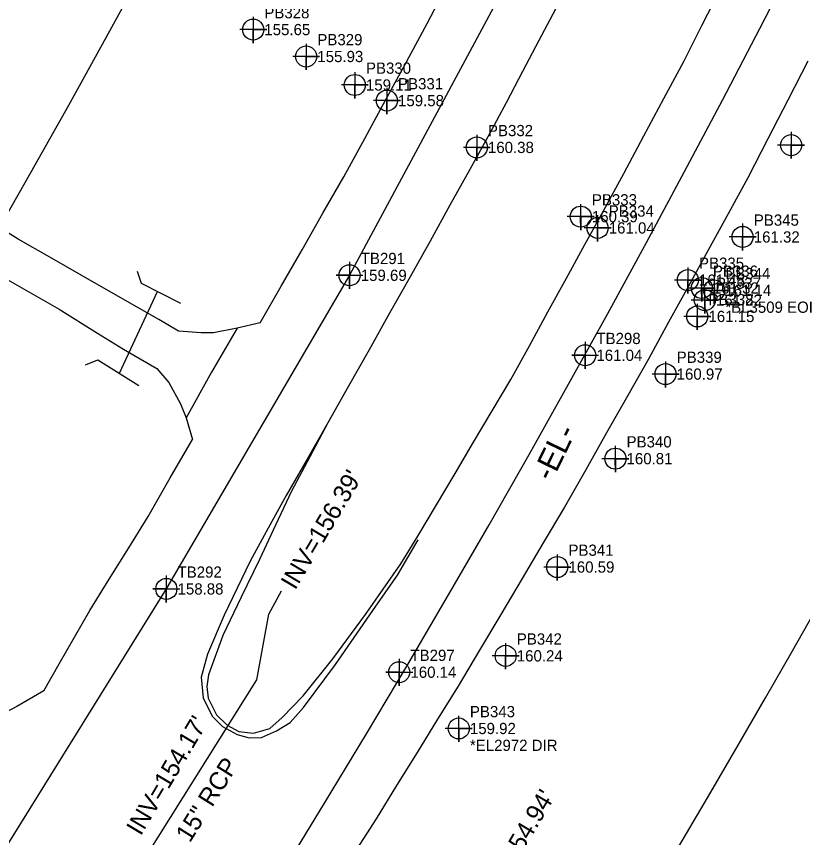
# Model space of a CAD drawing. Extents: x 2262665 to 2270527, y 505476 to 514960.
# Drawn here: x 2265830 to 2266005, y 508854 to 509036.7 of the extents above; entities that cross this region are included whole.
import ezdxf

# ---------------------------------------------------------------- set-up
doc = ezdxf.new("R2010")
doc.units = 0
for name, color, linetype in [('Exist Horizontal Alignment', 7, 'Continuous'), ('Exist Horizontal Alignment Direction Label', 7, 'Continuous'), ('Exist Right of Way Control of Access Line', 7, 'Continuous'), ('Exist Roads Change in Surface', 7, 'Continuous'), ('Exist Roads EOP', 7, 'Continuous'), ('Exist Roads EOP Other', 7, 'Continuous'), ('Exist Roads EOT', 7, 'Continuous'), ('Exist Roads EOT Cogo Elevation', 7, 'Continuous'), ('Exist Roads EOT Cogo Number', 7, 'Continuous'), ('Exist Roads EOT Cogo Point CELL', 7, 'Continuous'), ('Exist Structure Minor Culvert Topo', 7, 'Continuous'), ('Exist Structure Minor Head and End Wall', 7, 'Continuous'), ('Exist Structure Minor Pipes RCP 15 Inch', 7, 'Continuous'), ('Exist Structure Minor Pipes RCP 15 Inch Invert', 7, 'Continuous'), ('Exist Structure Minor Pipes RCP 15 Inch Leader', 7, 'Continuous'), ('Exist Structure Minor Pipes RCP 15 Inch Text', 7, 'Continuous'), ('Exist Utilities Telephone UG Cable SUE LOS C Cogo Comment', 7, 'Continuous'), ('Exist Utilities Telephone UG Cable SUE LOS C Cogo Elevation', 7, 'Continuous'), ('Exist Utilities Telephone UG Cable SUE LOS C Cogo Number', 7, 'Continuous'), ('Exist Utilities Telephone UG Cable SUE LOS C Cogo Point CELL', 7, 'Continuous'), ('Exist Utilities Telephone UG Conduit SUE LOS B Cogo Comment', 7, 'Continuous'), ('Exist Utilities Telephone UG Conduit SUE LOS B Cogo Elevation', 7, 'Continuous'), ('Exist Utilities Telephone UG Conduit SUE LOS B Cogo Number', 7, 'Continuous'), ('Exist Utilities Telephone UG Conduit SUE LOS B Cogo Point CELL', 7, 'Continuous')]:
    doc.layers.add(name, color=color, linetype=linetype)

msp = doc.modelspace()

# ---------------------------------------------------------------- linework, layer by layer
at = {"layer": 'Exist Horizontal Alignment'}
msp.add_arc((2263436.25, 510359.19), 2882, 309.60499, 355.6461, dxfattribs=at)
at = {"layer": 'Exist Right of Way Control of Access Line'}
for radius, end in [(2754.56, 355.6461), (2954.56, 339.73535)]:
    msp.add_arc((2263436.25, 510359.19), radius, 309.60499, end, dxfattribs=at)
at = {"layer": 'Exist Roads Change in Surface'}
msp.add_lwpolyline([(2265879.17, 508967.38), (2265873.46, 508957.58), (2265867.86, 508947.39)], dxfattribs=at)
at = {"layer": 'Exist Roads EOP'}
for points in [[(2265884.33, 508968.55), (2265888.98, 508976.67), (2265893.63, 508984.79), (2265898.28, 508992.91), (2265902.94, 509001.03), (2265907.58, 509009.55), (2265912.22, 509018.06), (2265916.86, 509026.58), (2265921.5, 509035.1), (2265927.16, 509046.11)], [(2265950.02, 509038.32), (2265946.36, 509031.38), (2265942.69, 509024.44), (2265939.03, 509017.5), (2265935.36, 509010.56), (2265930.94, 509002.62), (2265926.53, 508994.68), (2265922.11, 508986.74), (2265917.7, 508978.8), (2265913.12, 508970.67), (2265908.54, 508962.54), (2265903.96, 508954.41), (2265899.38, 508946.28), (2265895.32, 508938.69), (2265891.27, 508931.1), (2265887.72, 508923.5), (2265884.17, 508915.91), (2265880.07, 508907.46), (2265875.97, 508899), (2265872.78, 508890.2), (2265872.39, 508887.64), (2265872.74, 508885.01), (2265874.55, 508881.34), (2265876.97, 508879), (2265879.53, 508877.63), (2265882.84, 508877.23), (2265886.46, 508878.3), (2265889.21, 508880.7), (2265893.89, 508885.57), (2265900.48, 508893.74), (2265907.78, 508903.63), (2265911.68, 508909.28), (2265915.58, 508914.93), (2265919.39, 508921.1), (2265923.53, 508928.07), (2265927.68, 508935.04), (2265931.82, 508942.01), (2265935.96, 508948.98), (2265940.11, 508955.95), (2265944.23, 508963.45), (2265948.36, 508970.95), (2265952.49, 508978.45), (2265956.61, 508985.95), (2265960.74, 508993.45), (2265965.22, 509001.78), (2265969.7, 509010.12), (2265974.18, 509018.46), (2265978.66, 509026.8), (2265982.63, 509034.67), (2265986.61, 509042.54)], [(2266006.21, 509026.75), (2266001.77, 509018.09), (2265997.33, 509009.44), (2265992.89, 509000.78), (2265988.47, 508992.75), (2265984.05, 508984.72), (2265979.63, 508976.69), (2265975.21, 508968.66), (2265970.79, 508960.62), (2265966.11, 508952.36), (2265961.43, 508944.09), (2265956.76, 508935.82), (2265952.08, 508927.55), (2265947.33, 508919.58), (2265942.59, 508911.62), (2265937.85, 508903.65), (2265933.11, 508895.69), (2265928.36, 508887.72), (2265923.8, 508880.34), (2265919.24, 508872.97), (2265914.68, 508865.59), (2265910.12, 508858.21), (2265905.83, 508851.47)], [(2265836.16, 508886.67), (2265839.57, 508892.63), (2265842.98, 508898.6), (2265846.38, 508904.56), (2265850.7, 508911.53), (2265855.03, 508918.5), (2265859.35, 508925.47), (2265864.29, 508934.04), (2265869.22, 508942.6)]]:
    msp.add_lwpolyline(points, dxfattribs=at)
at = {"layer": 'Exist Roads EOP Other'}
for points in [[(2265884.33, 508968.55), (2265879.17, 508967.38), (2265873.94, 508966.34), (2265871.19, 508966.3), (2265866.15, 508966.71), (2265861.73, 508969.31), (2265852.09, 508974.77), (2265844.48, 508979.15), (2265837.47, 508983.14), (2265830.46, 508987.14), (2265822.19, 508992.25), (2265813.93, 508997.35), (2265805.95, 509001.85), (2265797.98, 509006.34), (2265797.27, 509009.51), (2265796.22, 509010.07)], [(2265789.44, 508998.23), (2265789.73, 508998.06), (2265792.8, 508998.29), (2265801.33, 508993.39), (2265805.02, 508991.37), (2265811.65, 508987.54), (2265818.28, 508983.71), (2265824.91, 508979.88), (2265832.25, 508975.72), (2265839.58, 508971.56), (2265848.07, 508966.25), (2265853.84, 508962.64), (2265861.31, 508958.35), (2265863.99, 508955.27), (2265866.59, 508950.54), (2265867.86, 508947.39), (2265869.22, 508942.6)], [(2265836.16, 508886.67), (2265830.16, 508883.15), (2265826.1, 508881.12)]]:
    msp.add_lwpolyline(points, dxfattribs=at)
at = {"layer": 'Exist Roads EOT'}
for points in [[(2265966, 509095.96), (2265942.58, 509050.45), (2265904.19, 508979.11), (2265863.41, 508909.33), (2265820.21, 508839.95), (2265775.13, 508772.3)], [(2265899.38, 508946.28), (2265894.74, 508938.21), (2265890.11, 508930.13), (2265886.1, 508922.82), (2265882.09, 508915.5), (2265876.32, 508903.52), (2265872.61, 508894.81), (2265871.18, 508889.7), (2265871.61, 508885.02), (2265873.68, 508880.95), (2265875.92, 508878.71), (2265879.19, 508876.91), (2265881.82, 508876.17), (2265884.58, 508876.28), (2265887.9, 508877.72), (2265891.01, 508879.6), (2265893.97, 508882.93), (2265901.06, 508892.54), (2265905.22, 508898.52), (2265909.39, 508904.5), (2265914.85, 508912.37), (2265919.44, 508920.23)]]:
    msp.add_lwpolyline(points, dxfattribs=at)
at = {"layer": 'Exist Roads EOT Cogo Point CELL'}
for points in [[(2265904.19, 508982.11), (2265904.19, 508976.11), (2265904.19, 508979.11), (2265901.19, 508979.11), (2265907.19, 508979.11)], [(2265956.65, 508964.31), (2265956.65, 508958.31), (2265956.65, 508961.31), (2265953.65, 508961.31), (2265959.65, 508961.31)], [(2265863.41, 508912.33), (2265863.41, 508906.33), (2265863.41, 508909.33), (2265860.41, 508909.33), (2265866.41, 508909.33)], [(2265915.25, 508893.8), (2265915.25, 508887.8), (2265915.25, 508890.8), (2265912.25, 508890.8), (2265918.25, 508890.8)]]:
    msp.add_lwpolyline(points, dxfattribs=at)
for centre in [(2265904.19, 508979.11), (2265956.65, 508961.31), (2265863.41, 508909.33), (2265915.25, 508890.8)]:
    msp.add_circle(centre, 2.34, dxfattribs=at)
at = {"layer": 'Exist Structure Minor Culvert Topo'}
msp.add_line((2265852.99, 508957.3), (2265861.44, 508975.48), dxfattribs=at)
at = {"layer": 'Exist Structure Minor Head and End Wall'}
for points in [[(2265866.65, 508972.82), (2265857.89, 508977.29), (2265857, 508979.96)], [(2265845.42, 508959.21), (2265848.19, 508960.28), (2265857.32, 508954.61)]]:
    msp.add_lwpolyline(points, dxfattribs=at)
at = {"layer": 'Exist Structure Minor Pipes RCP 15 Inch'}
msp.add_line((2265848.52, 508833.34), (2265883.53, 508889.1), dxfattribs=at)
at = {"layer": 'Exist Structure Minor Pipes RCP 15 Inch Leader'}
msp.add_lwpolyline([(2265883.53, 508889.1), (2265886.23, 508903.74), (2265889.08, 508908.92)], dxfattribs=at)
at = {"layer": 'Exist Utilities Telephone UG Cable SUE LOS C Cogo Point CELL'}
for points in [[(2266002.5, 509011.06), (2266002.5, 509005.06), (2266002.5, 509008.06), (2266005.5, 509008.06), (2265999.5, 509008.06)], [(2265991.69, 508990.64), (2265991.69, 508984.64), (2265991.69, 508987.64), (2265994.69, 508987.64), (2265988.69, 508987.64)], [(2265985.34, 508978.76), (2265985.34, 508972.76), (2265985.34, 508975.76), (2265988.34, 508975.76), (2265982.34, 508975.76)]]:
    msp.add_lwpolyline(points, dxfattribs=at)
for centre in [(2266002.5, 509008.06), (2265991.69, 508987.64), (2265985.34, 508975.76)]:
    msp.add_circle(centre, 2.34, dxfattribs=at)
at = {"layer": 'Exist Utilities Telephone UG Conduit SUE LOS B Cogo Point CELL'}
for points in [[(2265882.71, 509036.59), (2265882.75, 509030.78), (2265882.73, 509033.78), (2265885.75, 509033.78), (2265879.75, 509033.78)], [(2265894.51, 509030.6), (2265894.54, 509024.79), (2265894.53, 509027.79), (2265897.54, 509027.79), (2265891.54, 509027.79)], [(2265905.34, 509024.27), (2265905.37, 509018.45), (2265905.35, 509021.45), (2265908.37, 509021.45), (2265902.37, 509021.45)], [(2265912.48, 509020.79), (2265912.51, 509014.98), (2265912.49, 509017.98), (2265915.51, 509017.98), (2265909.51, 509017.98)], [(2265932.5, 509010.38), (2265932.53, 509004.56), (2265932.51, 509007.56), (2265935.53, 509007.56), (2265929.53, 509007.56)], [(2265955.62, 508994.97), (2265955.66, 508989.16), (2265955.64, 508992.16), (2265958.66, 508992.16), (2265952.66, 508992.16)], [(2265959.39, 508992.46), (2265959.42, 508986.65), (2265959.4, 508989.65), (2265962.42, 508989.65), (2265956.42, 508989.65)], [(2265979.48, 508980.87), (2265979.51, 508975.05), (2265979.49, 508978.05), (2265982.51, 508978.05), (2265976.51, 508978.05)], [(2265982.57, 508979.09), (2265982.6, 508973.28), (2265982.58, 508976.28), (2265985.6, 508976.28), (2265979.6, 508976.28)], [(2265983.25, 508976.41), (2265983.28, 508970.6), (2265983.26, 508973.6), (2265986.28, 508973.6), (2265980.28, 508973.6)], [(2265981.58, 508972.78), (2265981.61, 508966.96), (2265981.6, 508969.96), (2265984.61, 508969.96), (2265978.61, 508969.96)], [(2265974.51, 508959.95), (2265974.54, 508954.13), (2265974.52, 508957.13), (2265977.54, 508957.13), (2265971.54, 508957.13)], [(2265963.35, 508941.13), (2265963.38, 508935.31), (2265963.36, 508938.31), (2265966.38, 508938.31), (2265960.38, 508938.31)], [(2265950.41, 508917.01), (2265950.44, 508911.2), (2265950.43, 508914.2), (2265953.44, 508914.2), (2265947.44, 508914.2)], [(2265938.91, 508897.25), (2265938.95, 508891.44), (2265938.93, 508894.44), (2265941.95, 508894.44), (2265935.95, 508894.44)], [(2265928.47, 508881.1), (2265928.51, 508875.28), (2265928.49, 508878.28), (2265931.51, 508878.28), (2265925.51, 508878.28)]]:
    msp.add_lwpolyline(points, dxfattribs=at)
for centre in [(2265882.75, 509033.78), (2265894.54, 509027.79), (2265905.37, 509021.45), (2265912.51, 509017.98), (2265932.53, 509007.56), (2265955.66, 508992.16), (2265959.42, 508989.65), (2265979.51, 508978.05), (2265982.6, 508976.28), (2265983.28, 508973.6), (2265981.61, 508969.96), (2265974.54, 508957.13), (2265963.38, 508938.31), (2265950.44, 508914.2), (2265938.95, 508894.44), (2265928.51, 508878.28)]:
    msp.add_circle(centre, 2.34, dxfattribs=at)

# ---------------------------------------------------------------- texts
at = {"layer": 'Exist Horizontal Alignment Direction Label'}
msp.add_text('-EL-', height=5, rotation=64.085, dxfattribs=at).set_placement((2265949.24, 508933.04))
at = {"layer": 'Exist Roads EOT Cogo Elevation'}
for s, p in [('159.69', (2265906.69, 508977.86)), ('161.04', (2265959.15, 508960.06)), ('158.88', (2265865.91, 508908.08)), ('160.14', (2265917.75, 508889.55))]:
    msp.add_text(s, height=2.5, dxfattribs=at).set_placement(p)
at = {"layer": 'Exist Roads EOT Cogo Number'}
for s, p in [('TB291', (2265906.69, 508981.61)), ('TB298', (2265959.15, 508963.81)), ('TB292', (2265865.91, 508911.83)), ('TB297', (2265917.75, 508893.3))]:
    msp.add_text(s, height=2.5, dxfattribs=at).set_placement(p)
at = {"layer": 'Exist Structure Minor Pipes RCP 15 Inch Invert'}
for s, p in [("INV=156.39'", (2265892.09, 508908.92)), ("INV=154.17'", (2265857.71, 508854.22)), ("INV=154.94'", (2265935.04, 508837.82))]:
    msp.add_text(s, height=4, rotation=59.2519, dxfattribs=at).set_placement(p)
at = {"layer": 'Exist Structure Minor Pipes RCP 15 Inch Text'}
msp.add_text('15" RCP', height=4, rotation=57.874, dxfattribs=at).set_placement((2265868.64, 508852.69))
at = {"layer": 'Exist Utilities Telephone UG Cable SUE LOS C Cogo Comment'}
msp.add_text('*BL3509 EOI', height=2.5, dxfattribs=at).set_placement((2265987.84, 508970.76))
at = {"layer": 'Exist Utilities Telephone UG Cable SUE LOS C Cogo Elevation'}
for s, p in [('161.32', (2265994.19, 508986.39)), ('161.14', (2265987.84, 508974.51))]:
    msp.add_text(s, height=2.5, dxfattribs=at).set_placement(p)
at = {"layer": 'Exist Utilities Telephone UG Cable SUE LOS C Cogo Number'}
for s, p in [('PB345', (2265994.19, 508990.14)), ('PB344', (2265987.84, 508978.26))]:
    msp.add_text(s, height=2.5, dxfattribs=at).set_placement(p)
at = {"layer": 'Exist Utilities Telephone UG Conduit SUE LOS B Cogo Comment'}
msp.add_text('*EL2972 DIR', height=2.5, dxfattribs=at).set_placement((2265930.99, 508873.28))
at = {"layer": 'Exist Utilities Telephone UG Conduit SUE LOS B Cogo Elevation'}
for s, p in [('155.65', (2265885.23, 509032.53)), ('155.93', (2265897.03, 509026.54)), ('159.11', (2265907.85, 509020.2)), ('159.58', (2265914.99, 509016.73)), ('160.38', (2265935.01, 509006.31)), ('160.39', (2265958.14, 508990.91)), ('161.04', (2265961.9, 508988.4)), ('161.48', (2265981.99, 508976.8)), ('161.32', (2265985.08, 508975.03)), ('161.22', (2265985.76, 508972.35)), ('161.15', (2265984.1, 508968.71)), ('160.97', (2265977.02, 508955.88)), ('160.81', (2265965.86, 508937.06)), ('160.59', (2265952.93, 508912.95)), ('160.24', (2265941.43, 508893.19)), ('159.92', (2265930.99, 508877.03))]:
    msp.add_text(s, height=2.5, dxfattribs=at).set_placement(p)
at = {"layer": 'Exist Utilities Telephone UG Conduit SUE LOS B Cogo Number'}
for s, p in [('PB328', (2265885.23, 509036.28)), ('PB329', (2265897.03, 509030.29)), ('PB330', (2265907.85, 509023.95)), ('PB331', (2265914.99, 509020.48)), ('PB332', (2265935.01, 509010.06)), ('PB333', (2265958.14, 508994.66)), ('PB334', (2265961.9, 508992.15)), ('PB335', (2265981.99, 508980.55)), ('PB336', (2265985.08, 508978.78)), ('PB337', (2265985.76, 508976.1)), ('PB338', (2265984.1, 508972.46)), ('PB339', (2265977.02, 508959.63)), ('PB340', (2265965.86, 508940.81)), ('PB341', (2265952.93, 508916.7)), ('PB342', (2265941.43, 508896.94)), ('PB343', (2265930.99, 508880.78))]:
    msp.add_text(s, height=2.5, dxfattribs=at).set_placement(p)

doc.saveas('drawing.dxf')
